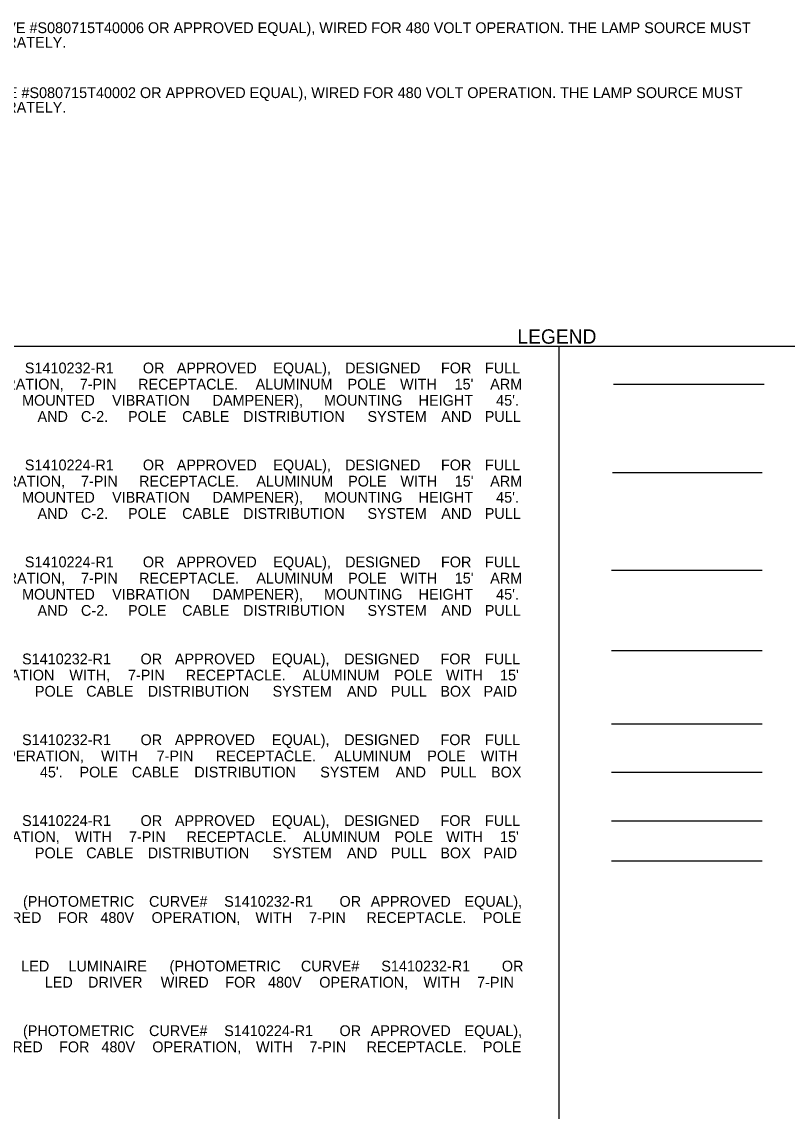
# Model space of a CAD drawing. Extents: x -1500 to -654, y -278 to 331.
# Drawn here: x -1188.7 to -975.5, y 27.5 to 330.8 of the extents above; entities that cross this region are included whole.
import ezdxf

# ---------------------------------------------------------------- set-up
doc = ezdxf.new("R2010")
doc.units = 0
for name, color, linetype in [('ConduitAG', 7, 'Continuous'), ('ConduitBM', 7, 'Continuous'), ('ConduitDB', 7, 'Continuous'), ('ConduitJB', 7, 'Continuous'), ('ConduitOT', 7, 'Continuous'), ('Default', 7, 'Continuous'), ('Miscellaneous3', 7, 'Continuous'), ('Miscellaneous8', 7, 'Continuous'), ('SheetBorder_dp', 7, 'Continuous')]:
    doc.layers.add(name, color=color, linetype=linetype)

msp = doc.modelspace()

# ---------------------------------------------------------------- linework, layer by layer
at = {"layer": 'ConduitAG'}
for p, q in [((-1024.44, 135.39), (-982.49, 135.39)), ((-1024.44, 121.9), (-982.49, 121.9)), ((-1024.44, 108.36), (-982.49, 108.36))]:
    msp.add_line(p, q, dxfattribs=at)
at = {"layer": 'ConduitBM'}
msp.add_line((-1024.45, 155.76), (-982.5, 155.76), dxfattribs=at)
at = {"layer": 'ConduitDB'}
msp.add_line((-1024.44, 178.13), (-982.49, 178.13), dxfattribs=at)
at = {"layer": 'ConduitJB'}
msp.add_line((-1024.19, 205.33), (-982.49, 205.33), dxfattribs=at)
at = {"layer": 'ConduitOT'}
msp.add_line((-1023.94, 229.93), (-981.99, 229.93), dxfattribs=at)
at = {"layer": 'Miscellaneous3'}
for p, q in [((-1424.17, 240.54), (-654.17, 240.54)), ((-1039.17, 240.54), (-1039.17, -233.32))]:
    msp.add_line(p, q, dxfattribs=at)
at = {"layer": 'Miscellaneous8'}
msp.add_line((-1024.44, 97.21), (-982.49, 97.21), dxfattribs=at)

# ---------------------------------------------------------------- texts
at = {"layer": 'Default'}
for s, height, p in [('WALL MOUNTED, 140 WATT LED LUMINAIRE WITH LED DRIVER (PHOTOMETRIC CURVE #S080715T40006 OR APPROVED EQUAL), WIRED FOR 480 VOLT OPERATION. THE LAMP SOURCE MUST ', 3, (-1357.1, 327.65)), ('MEET A CRI OF 21 (MIN) AND CCT OF 2100 K.  JUNCTION BOX TO BE PAID FOR SEPARATELY. ', 3, (-1357.1, 323.58)), ('WALL MOUNTED, 54 WATT LED LUMINAIRE WITH LED DRIVER (PHOTOMETRIC CURVE #S080715T40002 OR APPROVED EQUAL), WIRED FOR 480 VOLT OPERATION. THE LAMP SOURCE MUST ', 3, (-1357.1, 309.57)), ('MEET A CRI OF 21 (MIN) AND CCT OF 2100 K.  JUNCTION BOX TO BE PAID FOR SEPARATELY. ', 3, (-1357.1, 305.5)), ('LEGEND', 4, (-1050.67, 241.19))]:
    msp.add_text(s, height=height, dxfattribs=at).set_placement(p)
at = {"layer": 'SheetBorder_dp'}
for s, p in [('S1410232-R1 ', (-1187.86, 232.93)), ('OR ', (-1155.01, 232.93)), ('APPROVED ', (-1145.56, 232.93)), ('EQUAL), ', (-1118.68, 232.93)), ('DESIGNED ', (-1098.66, 232.93)), ('FOR ', (-1071.97, 232.93)), ('FULL ', (-1059.72, 232.93)), ('OPERATION, ', (-1201.77, 228.43)), ('7-PIN ', (-1172.56, 228.43)), ('RECEPTACLE. ', (-1156.33, 228.43)), ('ALUMINUM ', (-1123.6, 228.43)), ('POLE ', (-1097.99, 228.43)), ('WITH ', (-1083.38, 228.43)), ("15' ", (-1068.18, 228.43)), ('ARM ', (-1058.26, 228.43)), ('MOUNTED ', (-1188.65, 223.93)), ('VIBRATION ', (-1163.57, 223.93)), ('DAMPENER), ', (-1135.57, 223.93)), ('MOUNTING ', (-1104.55, 223.93)), ('HEIGHT ', (-1078.2, 223.93)), ("45'. ", (-1056.6, 223.93)), ('AND ', (-1184.34, 219.43)), ('C-2. ', (-1172.24, 219.43)), (' POLE ', (-1160.25, 219.43)), ('CABLE ', (-1144.06, 219.43)), ('DISTRIBUTION ', (-1127.08, 219.43)), ('SYSTEM ', (-1092.44, 219.43)), ('AND ', (-1071.88, 219.43)), ('PULL ', (-1059.78, 219.43)), ('S1410224-R1 ', (-1187.86, 205.93)), ('OR ', (-1155.01, 205.93)), ('APPROVED ', (-1145.56, 205.93)), ('EQUAL), ', (-1118.68, 205.93)), ('DESIGNED ', (-1098.66, 205.93)), ('FOR ', (-1071.97, 205.93)), ('FULL ', (-1059.72, 205.93)), ('OPERATION, ', (-1201.39, 201.43)), ('7-PIN ', (-1172.23, 201.43)), ('RECEPTACLE. ', (-1156.06, 201.43)), ('ALUMINUM ', (-1123.39, 201.43)), ('POLE ', (-1097.83, 201.43)), ('WITH ', (-1083.27, 201.43)), ("15' ", (-1068.13, 201.43)), ('ARM ', (-1058.26, 201.43)), ('MOUNTED ', (-1188.65, 196.93)), ('VIBRATION ', (-1163.57, 196.93)), ('DAMPENER), ', (-1135.57, 196.93)), ('MOUNTING ', (-1104.55, 196.93)), ('HEIGHT ', (-1078.2, 196.93)), ("45'. ", (-1056.6, 196.93)), ('AND ', (-1184.34, 192.43)), ('C-2. ', (-1172.24, 192.43)), (' POLE ', (-1160.25, 192.43)), ('CABLE ', (-1144.06, 192.43)), ('DISTRIBUTION ', (-1127.08, 192.43)), ('SYSTEM ', (-1092.44, 192.43)), ('AND ', (-1071.88, 192.43)), ('PULL ', (-1059.78, 192.43)), ('S1410224-R1 ', (-1187.86, 178.93)), ('OR ', (-1155.01, 178.93)), ('APPROVED ', (-1145.56, 178.93)), ('EQUAL), ', (-1118.68, 178.93)), ('DESIGNED ', (-1098.66, 178.93)), ('FOR ', (-1071.97, 178.93)), ('FULL ', (-1059.72, 178.93)), ('OPERATION, ', (-1201.39, 174.43)), ('7-PIN ', (-1172.23, 174.43)), ('RECEPTACLE. ', (-1156.06, 174.43)), ('ALUMINUM ', (-1123.39, 174.43)), ('POLE ', (-1097.83, 174.43)), ('WITH ', (-1083.27, 174.43)), ("15' ", (-1068.13, 174.43)), ('ARM ', (-1058.26, 174.43)), ('MOUNTED ', (-1188.65, 169.93)), ('VIBRATION ', (-1163.57, 169.93)), ('DAMPENER), ', (-1135.57, 169.93)), ('MOUNTING ', (-1104.55, 169.93)), ('HEIGHT ', (-1078.2, 169.93)), ("45'. ", (-1056.6, 169.93)), ('AND ', (-1184.34, 165.43)), ('C-2. ', (-1172.24, 165.43)), (' POLE ', (-1160.25, 165.43)), ('CABLE ', (-1144.06, 165.43)), ('DISTRIBUTION ', (-1127.08, 165.43)), ('SYSTEM ', (-1092.44, 165.43)), ('AND ', (-1071.88, 165.43)), ('PULL ', (-1059.78, 165.43)), ('S1410232-R1 ', (-1188.64, 151.93)), ('OR ', (-1155.65, 151.93)), ('APPROVED ', (-1146.08, 151.93)), ('EQUAL), ', (-1119.07, 151.93)), ('DESIGNED ', (-1098.92, 151.93)), ('FOR ', (-1072.1, 151.93)), ('FULL ', (-1059.72, 151.93)), ('OPERATION ', (-1203.27, 147.43)), ('WITH, ', (-1175.48, 147.43)), ('7-PIN ', (-1159.15, 147.43)), ('RECEPTACLE. ', (-1143.08, 147.43)), ('ALUMINUM ', (-1110.5, 147.43)), ('POLE ', (-1085.04, 147.43)), ('WITH ', (-1070.58, 147.43)), ("15' ", (-1055.53, 147.43)), ('POLE ', (-1185.07, 142.93)), ('CABLE ', (-1170.78, 142.93)), ('DISTRIBUTION ', (-1153.65, 142.93)), ('SYSTEM ', (-1118.87, 142.93)), ('AND ', (-1098.16, 142.93)), ('PULL ', (-1085.91, 142.93)), ('BOX ', (-1072.14, 142.93)), ('PAID ', (-1060.13, 142.93)), ('S1410232-R1 ', (-1188.64, 129.43)), ('OR ', (-1155.65, 129.43)), ('APPROVED ', (-1146.08, 129.43)), ('EQUAL), ', (-1119.07, 129.43)), ('DESIGNED ', (-1098.92, 129.43)), ('FOR ', (-1072.1, 129.43)), ('FULL ', (-1059.72, 129.43)), ('OPERATION, ', (-1196.16, 124.93)), ('WITH ', (-1166.66, 124.93)), ('7-PIN ', (-1151.18, 124.93)), ('RECEPTACLE. ', (-1134.68, 124.93)), ('ALUMINUM ', (-1101.67, 124.93)), ('POLE ', (-1075.78, 124.93)), ('WITH ', (-1060.89, 124.93)), ("45'. ", (-1183.68, 120.43)), ('POLE ', (-1172.65, 120.43)), ('CABLE ', (-1158.08, 120.43)), ('DISTRIBUTION ', (-1140.67, 120.43)), ('SYSTEM ', (-1105.6, 120.43)), ('AND ', (-1084.61, 120.43)), ('PULL ', (-1072.08, 120.43)), ('BOX ', (-1058.03, 120.43)), ('S1410224-R1 ', (-1188.64, 106.93)), ('OR ', (-1155.65, 106.93)), ('APPROVED ', (-1146.08, 106.93)), ('EQUAL), ', (-1119.07, 106.93)), ('DESIGNED ', (-1098.92, 106.93)), ('FOR ', (-1072.1, 106.93)), ('FULL ', (-1059.72, 106.93)), ('OPERATION, ', (-1202.89, 102.43)), ('WITH ', (-1173.88, 102.43)), ('7-PIN ', (-1158.88, 102.43)), ('RECEPTACLE. ', (-1142.86, 102.43)), ('ALUMINUM ', (-1110.34, 102.43)), ('POLE ', (-1084.93, 102.43)), ('WITH ', (-1070.52, 102.43)), ("15' ", (-1055.53, 102.43)), ('POLE ', (-1185.07, 97.93)), ('CABLE ', (-1170.78, 97.93)), ('DISTRIBUTION ', (-1153.65, 97.93)), ('SYSTEM ', (-1118.87, 97.93)), ('AND ', (-1098.16, 97.93)), ('PULL ', (-1085.91, 97.93)), ('BOX ', (-1072.14, 97.93)), ('PAID ', (-1060.13, 97.93)), ('(PHOTOMETRIC ', (-1188.39, 84.43)), ('CURVE# ', (-1153.28, 84.43)), ('S1410232-R1 ', (-1132.35, 84.43)), ('OR ', (-1100.24, 84.43)), ('APPROVED ', (-1091.55, 84.43)), ('EQUAL), ', (-1065.42, 84.43)), ('WIRED ', (-1196.63, 79.93)), ('FOR ', (-1178.67, 79.93)), ('480V ', (-1166.82, 79.93)), ('OPERATION, ', (-1152.58, 79.93)), ('WITH ', (-1123.63, 79.93)), ('7-PIN ', (-1108.71, 79.93)), ('RECEPTACLE. ', (-1092.76, 79.93)), ('POLE ', (-1060.3, 79.93)), ('LED ', (-1188.87, 66.43)), ('LUMINAIRE ', (-1175.73, 66.43)), ('(PHOTOMETRIC ', (-1147.57, 66.43)), ('CURVE# ', (-1110.98, 66.43)), ('S1410232-R1 ', (-1088.59, 66.43)), ('OR ', (-1055.02, 66.43)), ('LED ', (-1182.33, 61.93)), ('DRIVER ', (-1170.26, 61.93)), ('WIRED ', (-1150.03, 61.93)), ('FOR ', (-1132.04, 61.93)), ('480V ', (-1120.14, 61.93)), ('OPERATION, ', (-1105.86, 61.93)), ('WITH ', (-1076.88, 61.93)), ('7-PIN ', (-1061.91, 61.93)), ('(PHOTOMETRIC ', (-1188.39, 48.43)), ('EQUAL), ', (-1065.42, 48.43)), ('CURVE# ', (-1153.28, 48.43)), ('S1410224-R1 ', (-1132.35, 48.43)), ('OR ', (-1100.24, 48.43)), ('APPROVED ', (-1091.55, 48.43)), ('WIRED ', (-1196.25, 43.93)), ('FOR ', (-1178.35, 43.93)), ('480V ', (-1166.54, 43.93)), ('OPERATION, ', (-1152.36, 43.93)), ('WITH ', (-1123.47, 43.93)), ('7-PIN ', (-1108.6, 43.93)), ('RECEPTACLE. ', (-1092.7, 43.93)), ('POLE ', (-1060.3, 43.93))]:
    msp.add_text(s, height=3, dxfattribs=at).set_placement(p)

doc.saveas('drawing.dxf')
